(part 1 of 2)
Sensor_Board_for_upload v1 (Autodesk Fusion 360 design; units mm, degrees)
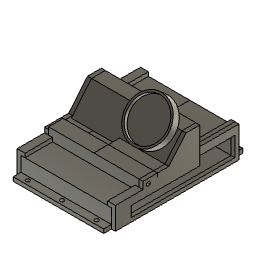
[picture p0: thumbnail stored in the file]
description: KiCad electronic assembly
part number: Sensor_Board 1
description: Part Number
part number: Sensor_Board 1.1.1
part number: Sensor_Board 1.1.2
part number: PinSocket-01x06_P2.54mm_Horizontal_SMD
part number: SoC_nRF_Sense
part number: Mic_nRF_Sense
part number: Antenna_nRF_Sense
part number: Board
part number: USB
part number: Contact
base_feature "Base Feature1"
base_feature "Base Feature1"
base_feature "Base Feature1"
base_feature "Base Feature1"
base_feature "Base Feature1"
base_feature "Base Feature1"
base_feature "Base Feature1"
place_component sketch "Sketch7"
base_feature "Base Feature1" sketch "Sketch7"
place_component sketch "Sketch7"
base_feature "Base Feature1" sketch "Sketch7"
base_feature "Base Feature1"
base_feature "Base Feature1"
base_feature "Base Feature1"
base_feature "Base Feature1"
base_feature "Base Feature1"
base_feature "Base Feature1"
base_feature "Base Feature1"
base_feature "Base Feature1"
base_feature "Base Feature1"
base_feature "Base Feature1"
place_component sketch "Sketch7"
base_feature "Base Feature1" sketch "Sketch7"
place_component sketch "Sketch7"
base_feature "Base Feature1" sketch "Sketch7"
place_component sketch "Sketch7"
base_feature "Base Feature1" sketch "Sketch7"
sketch "Sketch1" plane through (0, 0, 1.51) normal (0, 0, 1) x axis (-1, 0, 0)
  line L1 (-176.42, 128.48) -> (-136.51, 128.48)
  line L2 (-176.42, 91.11) -> (-176.42, 128.48)
  line L3 (-136.51, 91.11) -> (-176.42, 91.11)
  line L4 (-136.51, 128.48) -> (-136.51, 91.11)
  line L5 (-176.42, 91.11) -> (-136.51, 91.11)
  line L6 (-176.42, 128.48) -> (-176.42, 91.11)
  line L7 (-136.51, 128.48) -> (-176.42, 128.48)
  line L8 (-136.51, 91.11) -> (-136.51, 128.48)
  line L9 (-139, 115) -> (-157, 115)
  line L10 (-153, 101) -> (-143, 101)
  line L11 (-153, 92) -> (-153, 101)
  line L12 (-143, 92) -> (-153, 92)
  line L13 (-143, 101) -> (-143, 92)
  line L14 (-157.9717, 100.9445) -> (-136.51, 100.9445)
  line L15 (-157.9717, 115.3711) -> (-157.9717, 100.9445)
  line L16 (-136.51, 115.3711) -> (-157.9717, 115.3711)
  line L17 (-136.51, 100.9445) -> (-136.51, 115.3711)
  line L18 (-176.42, 92) -> (-162, 92)
  line L19 (-176.42, 127.4772) -> (-176.42, 92)
  line L20 (-162, 127.4772) -> (-176.42, 127.4772)
  line L21 (-162, 92) -> (-162, 127.4772)
  line L22 (-136.51, 107.3445) -> (-136.51, 100.9445)
  line L23 (-134, 107.4) -> (-134, 101)
  line L24 (-136.51, 112.3445) -> (-136.51, 107.3445)
  line L25 (-154.6841, 107.3445) -> (-136.51, 107.3445)
  line L26 (-154.6841, 112.46) -> (-154.6841, 107.3445)
  line L27 (-136.51, 112.46) -> (-154.6841, 112.46)
  line L28 (-136.51, 107.3445) -> (-136.51, 112.46)
  line L29 (-154.6841, 107.3445) -> (-136.51, 107.3445)
  line L30 (-154.6841, 112.46) -> (-154.6841, 107.3445)
  line L31 (-136.51, 112.46) -> (-154.6841, 112.46)
  line L32 (-136.51, 107.3445) -> (-136.51, 112.46)
  circle C1 centre (-140.465, 112.46) radius 0.4
  circle C2 centre (-140.465, 109.92) radius 0.4
  circle C3 centre (-140.465, 107.38) radius 0.4
  circle C4 centre (-155.7, 112.46) radius 0.4
  circle C5 centre (-155.7, 109.92) radius 0.4
  circle C6 centre (-155.7, 107.38) radius 0.4
  circle C7 centre (-140.465, 104.84) radius 0.4
  circle C8 centre (-140.465, 102.3) radius 0.4
  circle C9 centre (-140.465, 99.76) radius 0.4
  circle C10 centre (-140.465, 97.22) radius 0.4
  circle C11 centre (-155.7, 104.84) radius 0.4
  circle C12 centre (-155.7, 102.3) radius 0.4
  circle C13 centre (-155.7, 99.76) radius 0.4
  circle C14 centre (-155.7, 97.22) radius 0.4
  point P3 (-176.42, 128.48)
  point P22 (-176.42, 128.48)
  point P5 (-136.51, 91.11)
  point P20 (-136.51, 91.11)
  point P30 (-136.51, 100.9445)
  point P36 (-176.42, 127.4772)
  point P38 (-136.51, 107.3445)
  point P39 (-134, 101)
  point P40 (-134, 107.4)
  point P41 (-136.51, 112.3445)
  horizontal L5
  vertical L6
  horizontal L7
  vertical L8
  coincident P3 P22
  coincident P5 P20
  horizontal L9
  horizontal L10
  vertical L11
  horizontal L12
  vertical L13
  horizontal L14
  vertical L15
  horizontal L16
  vertical L17
  coincident L4 P30
  horizontal L18
  vertical L19
  horizontal L20
  vertical L21
  coincident L6 P36
  perpendicular L14 L22
  vertical L23
  parallel L4 L24
  horizontal L25
  vertical L26
  horizontal L27
  vertical L28
  horizontal L29
  vertical L30
  horizontal L31
  vertical L32
  dimension "d24" distance P30 P38 = 6.4
  dimension "d25" distance P39 P40 = 6.4
  dimension "d26" distance P38 P41 = 5
extrude "Extrude1" new body sketch "Sketch1" profile of L4 C1 C2 C3 C4 C5 C6 C7 C8 C11 C12 L8 L10 L11 L13 L14 L15 L16 L17 along normal blind 8.1
extrude "Extrude2" new body sketch "Sketch1" profile of L11 L12 L13 L14 along normal blind 4.7
extrude "Extrude3" new body sketch "Sketch1" profile of L2 L6 L18 L19 L20 L21 along normal blind 2.7
extrude "Extrude4" add of existing geometry to an object
extrude "Extrude5" add of existing geometry to an object
extrude "Extrude6" add of existing geometry to an object
extrude "Extrude7" add of existing geometry blind 1
extrude "Extrude8" add of existing geometry to an object
extrude "Extrude9" add of existing geometry blind 1.1
extrude "Extrude10" add sketch "Sketch1" profile of L1 L2 L3 L4 C1 C2 C3 C4 C5 C6 C7 C8 C9 C10 C11 C12 C13 C14 L5 L6 L7 L8 L10 L11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 against normal blind 1.3
shell "Shell1" outerThickness 2
delete_face "DeleteFace1"
extrude "Extrude11" cut of existing geometry blind -11
extrude "Extrude1" cut sketch "Sketch1" profile of L4 C1 C2 C3 L8 L17 L29 L30 L31 L32 along normal blind 10
extrude "Extrude2" cut sketch "Sketch1" profile of L4 C1 C2 C3 L8 L17 L29 L30 L31 L32 along normal blind 10
extrude "Extrude3" cut sketch "Sketch1" profile of L4 C1 C2 C3 L8 L17 L29 L30 L31 L32 along normal blind 12.5
extrude "Extrude13" add of existing geometry to an object
sketch "Sketch2" plane through (178.42, 0, 0) normal (1, 0, 0) x axis (0, 1, 0)
  line L1 (-89, 6.21) -> (-89, -1.79)
  line L2 (-130.5772, 6.21) -> (-89, 6.21)
  line L3 (-130.5772, -0.49) -> (-130.5772, 6.21)
  line L4 (-130.48, -0.49) -> (-130.5772, -0.49)
  line L5 (-130.48, -1.79) -> (-130.48, -0.49)
  line L6 (-89, -1.79) -> (-130.48, -1.79)
  line L7 (-129.7046, 5.3373) -> (-89.8727, 5.3373)
  line L8 (-129.7046, 0.3827) -> (-129.7046, 5.3373)
  line L9 (-129.6073, 0.3827) -> (-129.7046, 0.3827)
  line L10 (-129.6073, -0.9173) -> (-129.6073, 0.3827)
  line L11 (-89.8727, -0.9173) -> (-129.6073, -0.9173)
  line L12 (-89.8727, 5.3373) -> (-89.8727, -0.9173)
  dimension "d57" = -0.8727
extrude "Extrude14" cut sketch "Sketch2" profile of L7 L8 L10 L11 L12 L9 against normal blind 4
sketch "Sketch3" plane through (0, -89, 0) normal (0, 1, 0) x axis (-1, 0, 0)
  line L1 (-159.9717, 8.21) -> (-136.51, 8.21)
  line L2 (-159.9717, 6.21) -> (-159.9717, 8.21)
  line L3 (-178.42, 6.21) -> (-159.9717, 6.21)
  line L4 (-178.42, -1.79) -> (-178.42, 6.21)
  line L5 (-136.51, -1.79) -> (-178.42, -1.79)
  line L6 (-136.51, 8.21) -> (-136.51, -1.79)
  line L7 (-141.3021, 7) -> (-155, 7)
  line L8 (-141.3021, 2.7647) -> (-141.3021, 7)
  line L9 (-155, 2.7647) -> (-141.3021, 2.7647)
  line L10 (-155, 7) -> (-155, 2.7647)
  horizontal L7
  vertical L8
  horizontal L9
  vertical L10
extrude "Extrude15" cut sketch "Sketch3" profile of L7 L8 L9 L10 against normal blind 2
extrude "Extrude16" add of existing geometry blind 10
extrude "Extrude17" add of existing geometry to an object
extrude "Extrude18" add of existing geometry to an object
sketch "Sketch4" plane through (136.51, 0, 0) normal (-1, 0, 0) x axis (0, -1, 0)
  line L1 (112.46, 9.61) -> (112.46, 11.61)
  line L2 (115.3711, 9.61) -> (112.46, 9.61)
  line L3 (115.3711, 4.21) -> (115.3711, 9.61)
  line L4 (128.5772, 4.21) -> (115.3711, 4.21)
  line L5 (128.5772, 1.51) -> (128.5772, 4.21)
  line L6 (128.48, 1.51) -> (128.5772, 1.51)
  line L7 (128.48, 0.21) -> (128.48, 1.51)
  line L8 (91.11, 0.21) -> (128.48, 0.21)
  line L9 (91.11, 1.51) -> (91.11, 0.21)
  line L10 (91, 1.51) -> (91.11, 1.51)
  line L11 (91, 6.21) -> (91, 1.51)
  line L12 (100.9445, 6.21) -> (91, 6.21)
  line L13 (100.9445, 9.61) -> (100.9445, 6.21)
  line L14 (107.3445, 9.61) -> (100.9445, 9.61)
  line L15 (107.3445, 11.61) -> (107.3445, 9.61)
  line L16 (89, 11.61) -> (107.3445, 11.61)
  line L17 (89, -1.79) -> (89, 11.61)
  line L18 (130.48, -1.79) -> (89, -1.79)
  line L19 (130.48, -0.49) -> (130.48, -1.79)
  line L20 (130.5772, -0.49) -> (130.48, -0.49)
  line L21 (130.5772, 6.21) -> (130.5772, -0.49)
  line L22 (117.3711, 6.21) -> (130.5772, 6.21)
  line L23 (117.3711, 11.61) -> (117.3711, 6.21)
  line L24 (112.46, 11.61) -> (117.3711, 11.61)
  line L25 (97.0599, 23.8667) -> (107.3445, 11.61)
  line L26 (123.3445, 11.61) -> (107.3445, 11.61)
  line L27 (97.0599, 11.61) -> (97.0599, 23.8667)
  line L28 (96, 23.8667) -> (97.0599, 23.8667)
  line L29 (96, 11.61) -> (96, 23.8667)
  point P17 (107.3445, 11.61)
  point P26 (107.3445, 11.61)
  point P29 (97.0599, 11.61)
  point P31 (96, 11.61)
  point P27 (97.0599, 23.8667)
  horizontal L26
  coincident P17 P26
  coincident L16 P29
  perpendicular L16 L27
  perpendicular L27 L28
  coincident L16 P31
  perpendicular L16 L29
  dimension "d68" angle L25 L26 = 130
  dimension "d69" distance P26 P27 = 16
extrude "Extrude19" add sketch "Sketch4" profile of L16 L25 L27 L28 L29 to an object
extrude "Extrude20" add of existing geometry blind 2
extrude "Extrude21" add of existing geometry blind 5
sketch "Sketch5" plane through (0, 0, -0.49) normal (0, 0, 1) x axis (-1, 0, 0)
  line L1 (-136.51, 130.5772) -> (-178.42, 130.5772)
  line L2 (-136.51, 135.48) -> (-136.51, 130.5772)
  line L3 (-178.42, 135.48) -> (-136.51, 135.48)
  line L4 (-178.42, 130.5772) -> (-178.42, 135.48)
  circle C1 centre (-176.1314, 133.0286) radius 1
  circle C2 centre (-157.6314, 133.0286) radius 1
  circle C3 centre (-139.1314, 133.0286) radius 1
  dimension "d86" diameter C1 = 2
  dimension "d89" R-Pattern1-uDistance = 37
  dimension "d90" R-Pattern1-vDistance = 0
extrude "Extrude22" cut sketch "Sketch5" profile of C1 C2 C3 against normal blind 2
extrude "Extrude23" add of existing geometry blind 19
offset_faces "OffsetFaces1" distance -1
extrude "Extrude24" cut of existing geometry blind -0.5 taper 1 (= "deg")
sketch "Sketch6" plane through (0, -67.9431, 57.011) normal (0, -0.766, 0.6428) x axis (1, 0, 0)
  line L1 (136.51, -43.6488) -> (178.9717, -43.6488)
  line L2 (136.51, -59.742) -> (136.51, -43.6488)
  line L3 (154.6841, -59.742) -> (136.51, -59.742)
  line L4 (154.6841, -59.2668) -> (154.6841, -59.742)
  line L5 (178.9717, -59.2668) -> (154.6841, -59.2668)
  line L6 (178.9717, -43.6488) -> (178.9717, -59.2668)
  line L7 (155.6335, -43.6488) -> (141.6335, -43.6488)
  line L8 (155.6335, -57.6488) -> (155.6335, -43.6488)
  line L9 (141.6335, -57.6488) -> (155.6335, -57.6488)
  line L10 (141.6335, -43.6488) -> (141.6335, -57.6488)
  point P8 (141.6335, -43.6488)
  point P9 (155.6335, -43.6488)
  point P11 (141.6335, -57.6488)
  horizontal L7
  vertical L8
  horizontal L9
  vertical L10
  coincident L1 P8
  dimension "d100" distance P8 P9 = 14
  dimension "d101" distance P8 P11 = 14
extrude "Extrude25" new body sketch "Sketch6" profile of L1 L7 L8 L9 L10 along normal blind 4
extrude "Extrude26" add of existing geometry blind 3
extrude "Extrude27" add of existing geometry to an object
sketch "Sketch7" plane through (0, -89, 0) normal (0, 1, 0) x axis (-1, 0, 0)
  line L1 (-141.3021, 2.7647) -> (-141.3021, 7)
  line L2 (-155, 2.7647) -> (-141.3021, 2.7647)
  line L3 (-155, 7) -> (-155, 2.7647)
  line L4 (-141.3021, 7) -> (-155, 7)
  line L5 (-136.51, 11.61) -> (-136.51, -1.79)
  line L6 (-181.9717, 11.61) -> (-136.51, 11.61)
  line L7 (-181.9717, -1.79) -> (-181.9717, 11.61)
  line L8 (-136.51, -1.79) -> (-181.9717, -1.79)
  line L9 (-156.7, 1.0647) -> (-139.6021, 1.0647)
  line L10 (-156.7, 8.7) -> (-156.7, 1.0647)
  line L11 (-139.6021, 8.7) -> (-156.7, 8.7)
  line L12 (-139.6021, 1.0647) -> (-139.6021, 8.7)
  dimension "d108" = -1.7
extrude "Extrude4" cut sketch "Sketch7" profile of L1 L2 L3 L4 L11 L12 L10 L9 against normal blind 11
extrude "Extrude29" cut of existing geometry to an object
position "Position1"
extrude "Extrude30" add of existing geometry to an object
extrude "Extrude31" add of existing geometry blind 7
extrude "Extrude32" add blind 7
extrude "Extrude33" cut of existing geometry to an object
extrude "Extrude34" add of existing geometry to an object
sketch "Sketch8" plane through (0, -67.9431, 57.011) normal (0, -0.766, 0.6428) x axis (1, 0, 0)
  circle C1 centre (170, -46) radius 11.5
  circle C2 centre (170, -46) radius 10.25
  concentric C1 C2
  dimension "d135" diameter C1 = 23
  dimension "d136" diameter C2 = 20.5
extrude "Extrude35" add sketch "Sketch8" against normal blind 2
extrude "Extrude36" add sketch "Sketch8" along normal blind 2
sketch "Sketch9" plane through (0, 0, 0) normal (1, 0, 0) x axis (0, 1, 0)
  line L1 (-129.7046, 5.3373) -> (-129.7046, 0.3827)
  line L2 (-89.8727, 5.3373) -> (-129.7046, 5.3373)
  line L3 (-89.8727, -0.9173) -> (-89.8727, 5.3373)
  line L4 (-129.6073, -0.9173) -> (-89.8727, -0.9173)
  line L5 (-129.6073, 0.3827) -> (-129.6073, -0.9173)
  line L6 (-129.7046, 0.3827) -> (-129.6073, 0.3827)
  line L7 (-106.0391, 11.61) -> (-96, 23.5741)
  line L8 (-117.3711, 11.61) -> (-106.0391, 11.61)
  line L9 (-117.3711, 6.21) -> (-117.3711, 11.61)
  line L10 (-130.5772, 6.21) -> (-117.3711, 6.21)
  line L11 (-130.5772, -0.49) -> (-130.5772, 6.21)
  line L12 (-135.48, -0.49) -> (-130.5772, -0.49)
  line L13 (-135.48, -1.79) -> (-135.48, -0.49)
  line L14 (-89, -1.79) -> (-135.48, -1.79)
  line L15 (-89, 23.5741) -> (-89, -1.79)
  line L16 (-96, 23.5741) -> (-89, 23.5741)
  line L17 (-72, -1.79) -> (-89, -1.79)
  line L18 (-72, -0.79) -> (-72, -1.79)
  line L19 (-89, -0.79) -> (-72, -0.79)
  line L20 (-89, -1.79) -> (-89, -0.79)
  point P16 (-89, -1.79)
  point P18 (-89, -1.79)
  point P19 (-72, -1.79)
  point P21 (-89, -0.79)
  horizontal L17
  vertical L18
  horizontal L19
  vertical L20
  coincident P16 P18
  dimension "d141" distance P18 P19 = 17
  dimension "d142" distance P18 P21 = 1
sketch "Sketch1" plane through (-0.0036, 0, 0) normal (1, 0, 0) x axis (0, 1, 0)
  line L1 (-106.2762, 11.1776) -> (-106.2762, 10.0416)
  line L2 (-71.0417, 0.1416) -> (-91.0417, 0.1416)
  line L3 (-115.7809, 5.5) -> (-115.7809, 10)
  line L4 (-129.7809, 5.5) -> (-115.7809, 5.5)
  line L5 (-129.7809, 0.1416) -> (-129.7809, 5.5)
  line L6 (-110.3917, 8.5692) -> (-110.3917, 11.1776)
  line L7 (-106.2762, 8.5692) -> (-110.3917, 8.5692)
  line L8 (-106.2762, 11.1776) -> (-106.2762, 8.5692)
  line L9 (-88.9317, 10) -> (-88.9317, 23.5057)
  line L10 (-106.2762, 10.0416) -> (-106.2762, 11.1776)
  line L11 (-88.9317, 23.5057) -> (-88.9317, 10)
  line L12 (-71.0417, 0.1416) -> (-71.0417, 10)
  line L13 (-129.7809, 0.1416) -> (-91.0417, 0.1416)
  line L14 (-106.2762, 11.1776) -> (-95.9317, 23.5057)
  line L15 (-71.0417, 10) -> (-88.9317, 10.0211)
  line L16 (-95.9317, 23.5057) -> (-88.9317, 23.5057)
  line L17 (-135.7809, 0.1416) -> (-129.7809, 0.1416)
  line L18 (-100.5425, 11.1416) -> (-100.5425, 10.0348)
  line L19 (-106.2762, 11.1776) -> (-100.5425, 11.1416)
  line L20 (-110.3917, 11.1776) -> (-110.3917, 9.8734)
  line L21 (-116.3456, 11.1416) -> (-100.5425, 11.1416)
  line L22 (-115.7809, 11.1416) -> (-115.7809, 10)
  line L23 (-110.3917, 11.1776) -> (-115.7809, 11.1416)
  line L24 (-100.5425, 0.1416) -> (-100.5425, 11.1416)
  line L25 (-110.4051, 13.1776) -> (-117.7809, 13.1283)
  line L26 (-117.7809, 13.1283) -> (-117.7809, 10)
  line L27 (-117.7809, 7.5) -> (-117.7809, 10)
  line L28 (-131.7809, 7.5) -> (-117.7809, 7.5)
  line L29 (-131.7809, 0.1416) -> (-131.7809, 7.5)
  line L30 (-110.3917, 11.1776) -> (-110.4051, 13.1776)
  line L31 (-135.7809, 0.1416) -> (-131.7809, 0.1416)
  line L32 (-131.7809, -4.6856) -> (-131.7809, 1.0452)
  line L33 (-128, -1.8584) -> (-131.727, -1.8584)
  line L34 (-131.7809, -1.8584) -> (-71.0417, -1.8584)
  line L35 (-131.7809, 0.1416) -> (-131.7809, -1.8584)
  line L36 (-135.78, -1.8416) -> (-131.7809, -1.8584)
  line L37 (-135.7809, 0.1416) -> (-135.78, -1.8416)
  line L38 (-71.0417, -1.8584) -> (-71.0417, 0.5196)
  line L39 (-69.0417, 11.9976) -> (-88.9293, 12.0211)
  line L40 (-69.0417, -1.8584) -> (-69.0417, 11.9976)
  line L41 (-69.0417, -1.8584) -> (-91.0417, -1.8584)
  line L42 (-129.7809, -1.8584) -> (-91.0417, -1.8584)
  line L43 (-88.9317, 10) -> (-88.9293, 12.0211)
  line L44 (-65.0417, -1.8584) -> (-69.0417, -1.8584)
  line L45 (-65.0417, 0.319) -> (-65.0417, -1.8584)
  line L46 (-69.0417, 0.319) -> (-65.0417, 0.319)
  line L47 (-69.0417, -1.8584) -> (-69.0417, 0.319)
  line L48 (-100.5425, 10.0348) -> (-88.9317, 10)
  line L49 (-71.0417, 0.319) -> (-69.0417, 0.319)
  point P3 (-106.2762, 11.1776)
  point P11 (-106.2762, 11.1776)
  point P2 (-106.2762, 10.0416)
  point P18 (-106.2762, 10.0416)
  point P21 (-106.2762, 11.1776)
  point P23 (-110.3917, 9.8734)
  point P25 (-115.7809, 11.1416)
  point P26 (-100.5425, 0.1416)
  point P33 (-88.9317, 10.0211)
  point P35 (-131.7809, 1.0452)
  point P38 (-131.7809, -1.8584)
  point P40 (-71.0417, 0.5196)
  point P4 (-91.0417, 0.1416)
  point P5 (-71.0417, 0.1416)
  point P7 (-115.7809, 10)
  point P8 (-115.7809, 5.5)
  point P9 (-129.7809, 5.5)
  point P10 (-129.7809, 0.1416)
  point P19 (-135.7809, 0.1416)
  point P44 (-69.0417, -1.8584)
  point P47 (-65.0417, -1.8584)
  vertical L6
  horizontal L7
  vertical L8
  coincident P3 P11
  coincident P2 P18
  perpendicular L5 L13
  horizontal L16
  perpendicular L5 L17
  vertical L18
  coincident P3 P21
  midpoint L6 P23
  perpendicular L18 L21
  coincident L21 P25
  perpendicular L21 L22
  coincident L13 P26
  perpendicular L13 L24
  perpendicular L23 L30
  coincident L9 P33
  parallel L17 L31
  coincident L29 P35
  perpendicular L31 L32
  perpendicular L32 L33
  coincident L32 P38
  perpendicular L32 L34
  perpendicular L17 L35
  coincident L12 P40
  perpendicular L34 L38
  horizontal L44
  vertical L45
  horizontal L46
  vertical L47
  horizontal L49
  perpendicular L38 L49
  dimension "d143" distance P4 P5 = 20
  dimension "d145" distance P7 P8 = 4.5
  dimension "d146" distance P8 P9 = 14
  dimension "d147" distance P10 P19 = 6
  dimension "d150" = -2
  dimension "d154" = 2
  dimension "d155" distance P44 P47 = 4
extrude "Extrude1" new body sketch "Sketch1" profile of L2 L3 L4 L5 L9 L11 L12 L13 L14 L15 L16 L17 L18 L19 L22 L23 L24 L26 L28 L27 L29 L25 L30 L31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 along normal blind 23
sketch "Sketch2" plane through (22.9964, 0, 0) normal (1, 0, 0) x axis (0, 1, 0)
  line L1 (-95.9317, 23.5057) -> (-88.9317, 23.5057)
  line L2 (-106.2762, 11.1776) -> (-95.9317, 23.5057)
  line L3 (-100.5425, 11.1416) -> (-106.2762, 11.1776)
  line L4 (-100.5425, 10.0348) -> (-100.5425, 11.1416)
  line L5 (-88.9317, 10) -> (-100.5425, 10.0348)
  line L6 (-88.9317, 23.5057) -> (-88.9317, 10)
  line L7 (-65.0417, -1.8584) -> (-131.7809, -1.8584)
  line L8 (-65.0417, 0.319) -> (-65.0417, -1.8584)
  line L9 (-69.0417, 0.319) -> (-65.0417, 0.319)
  line L10 (-69.0417, 11.9976) -> (-69.0417, 0.319)
  line L11 (-88.9293, 12.0211) -> (-69.0417, 11.9976)
  line L12 (-88.9317, 10.0211) -> (-88.9293, 12.0211)
  line L13 (-71.0417, 10) -> (-88.9317, 10.0211)
  line L14 (-71.0417, 0.1416) -> (-71.0417, 10)
  line L15 (-129.7809, 0.1416) -> (-71.0417, 0.1416)
  line L16 (-129.7809, 5.5) -> (-129.7809, 0.1416)
  line L17 (-115.7809, 5.5) -> (-129.7809, 5.5)
  line L18 (-115.7809, 11.1416) -> (-115.7809, 5.5)
  line L19 (-110.3917, 11.1776) -> (-115.7809, 11.1416)
  line L20 (-110.4051, 13.1776) -> (-110.3917, 11.1776)
  line L21 (-117.7809, 13.1283) -> (-110.4051, 13.1776)
  line L22 (-117.7809, 7.5) -> (-117.7809, 13.1283)
  line L23 (-131.7809, 7.5) -> (-117.7809, 7.5)
  line L24 (-131.7809, 0.1416) -> (-131.7809, 7.5)
  line L25 (-135.7809, 0.1416) -> (-131.7809, 0.1416)
  line L26 (-135.78, -1.8416) -> (-135.7809, 0.1416)
  line L27 (-131.7809, -1.8584) -> (-135.78, -1.8416)
  line L28 (-117.7224, 5.5) -> (-117.7224, 11.9976)
  line L29 (-69.0417, 5.5) -> (-117.7224, 5.5)
  line L30 (-69.0417, 11.9976) -> (-69.0417, 5.5)
  line L31 (-110.3917, 13.1776) -> (-110.4051, 13.1776)
  line L32 (-110.3917, 11.1776) -> (-110.3917, 13.1776)
  line L33 (-110.4051, 11.1776) -> (-110.3917, 11.1776)
  line L34 (-110.4051, 13.1776) -> (-110.4051, 11.1776)
  line L35 (-110.3917, 13.1776) -> (-110.4051, 13.1776)
  line L36 (-110.3917, 11.1776) -> (-110.3917, 13.1776)
  line L37 (-110.4051, 11.1776) -> (-110.3917, 11.1776)
  line L38 (-110.4051, 13.1776) -> (-110.4051, 11.1776)
  line L39 (-88.9374, 11.9976) -> (-88.9374, 13.1283)
  line L40 (-117.7809, 8.2745) -> (-90.4296, 8.2745)
  line L41 (-117.7809, 13.1283) -> (-117.7809, 8.2745)
  line L42 (-95.9317, 23.5057) -> (-106.2762, 11.1776)
  line L43 (-88.9293, 12.0211) -> (-88.9317, 23.5057)
  line L44 (-88.9317, 23.5057) -> (-95.9317, 23.5057)
  line L45 (-88.9317, 23.5057) -> (-95.9317, 23.5057)
  line L46 (-97.5297, 10.0174) -> (-90.998, 10.0174)
  line L47 (-95.2322, 22.0057) -> (-102.3675, 13.5022)
  line L48 (-90.4314, 22.0057) -> (-95.2322, 22.0057)
  line L49 (-90.4296, 13.519) -> (-90.4314, 22.0057)
  line L50 (-102.3675, 13.5022) -> (-99.0604, 13.5068)
  line L51 (-90.998, 11.9976) -> (-90.998, 12.0182)
  line L52 (-99.0604, 10.0174) -> (-90.998, 10.0174)
  line L53 (-99.0604, 13.5068) -> (-99.0604, 10.0174)
  line L54 (-99.0604, 8.2745) -> (-99.0604, 10.0174)
  line L55 (-102.3675, 13.5022) -> (-99.0604, 13.5068)
  line L56 (-88.9374, 12.0211) -> (-88.9293, 12.0211)
  line L57 (-105.5881, 11.9976) -> (-99.0604, 12.0068)
  line L58 (-88.9374, 11.9976) -> (-69.0417, 11.9976)
  line L59 (-117.7224, 11.9976) -> (-99.0604, 11.9976)
  line L60 (-99.0604, 13.1283) -> (-117.7809, 13.1283)
  line L61 (-88.9374, 12.0211) -> (-88.9293, 12.0211)
  line L62 (-105.5881, 11.9976) -> (-99.0604, 12.0068)
  line L63 (-90.4296, 8.2745) -> (-90.4296, 13.519)
  point P31 (-117.7224, 5.5)
  point P12 (-69.0417, 11.9976)
  point P29 (-69.0417, 11.9976)
  point P21 (-110.3917, 11.1776)
  point P35 (-110.3917, 11.1776)
  point P22 (-110.4051, 13.1776)
  point P33 (-110.4051, 13.1776)
  point P23 (-117.7809, 13.1283)
  point P39 (-117.7809, 13.1283)
  point P4 (-106.2762, 11.1776)
  point P42 (-106.2762, 11.1776)
  point P3 (-95.9317, 23.5057)
  point P43 (-95.9317, 23.5057)
  point P2 (-88.9317, 23.5057)
  point P44 (-88.9317, 23.5057)
  point P13 (-88.9293, 12.0211)
  point P45 (-88.9293, 12.0211)
  point P46 (-95.9317, 23.5057)
  point P47 (-88.9317, 23.5057)
  point P48 (-88.9293, 12.0211)
  point P49 (-105.5881, 11.9976)
  point P58 (-99.0604, 8.2745)
  point P60 (-99.0604, 12.0068)
  point P62 (-99.0604, 11.9976)
  point P63 (-99.0604, 13.1283)
  point P64 (-88.9374, 12.0211)
  horizontal L58
  vertical L28
  horizontal L29
  vertical L30
  coincident L17 P31
  coincident P12 P29
  horizontal L31
  vertical L32
  horizontal L33
  vertical L34
  coincident P21 P35
  coincident P22 P33
  horizontal L35
  vertical L36
  horizontal L37
  vertical L38
  horizontal L60
  vertical L39
  horizontal L40
  vertical L41
  coincident P23 P39
  coincident P4 P42
  coincident P3 P43
  coincident P2 P44
  coincident P13 P45
  coincident P3 P46
  coincident P2 P47
  coincident P13 P48
  coincident P49 L58
  coincident L42 P49
  horizontal L46
  vertical L51
  horizontal L52
  vertical L53
  coincident L40 P58
  perpendicular L40 L54
  parallel L50 L55
  coincident L53 P60
  collinear L56 L57
  coincident L53 P62
  collinear L58 L59
  coincident L53 P63
  collinear L61 L62
  coincident L39 P64
  perpendicular L40 L63
sketch "Sketch3" plane through (40.9964, 0, 0) normal (1, 0, 0) x axis (0, 1, 0)
  line L1 (-95.2322, 22.0057) -> (-102.3675, 13.5022)
  line L2 (-90.4314, 22.0057) -> (-95.2322, 22.0057)
  line L3 (-90.4296, 13.519) -> (-90.4314, 22.0057)
  line L4 (-102.3675, 13.5022) -> (-99.0604, 13.5068)
  line L5 (-88.9317, 12.0211) -> (-88.9374, 12.0211)
  line L6 (-88.9317, 11.9976) -> (-88.9317, 10)
  line L7 (-95.9317, 23.5057) -> (-88.9317, 23.5057)
  line L8 (-104.6394, 13.1283) -> (-95.9317, 23.5057)
  line L9 (-110.3917, 13.1283) -> (-104.6394, 13.1283)
  line L10 (-110.3917, 11.1776) -> (-110.3917, 13.1283)
  line L11 (-110.4051, 11.1776) -> (-110.3917, 11.1776)
  line L12 (-110.4051, 13.1283) -> (-110.4051, 11.1776)
  line L13 (-117.7809, 13.1283) -> (-110.4051, 13.1283)
  line L14 (-117.7809, 7.5) -> (-117.7809, 13.1283)
  line L15 (-131.7809, 7.5) -> (-117.7809, 7.5)
  line L16 (-131.7809, 0.1416) -> (-131.7809, 7.5)
  line L17 (-135.7809, 0.1416) -> (-131.7809, 0.1416)
  line L18 (-135.78, -1.8416) -> (-135.7809, 0.1416)
  line L19 (-131.7809, -1.8584) -> (-135.78, -1.8416)
  line L20 (-65.0417, -1.8584) -> (-131.7809, -1.8584)
  line L21 (-65.0417, 0.319) -> (-65.0417, -1.8584)
  line L22 (-69.0417, 0.319) -> (-65.0417, 0.319)
  line L23 (-69.0417, 11.9976) -> (-69.0417, 0.319)
  line L24 (-88.9293, 11.9976) -> (-69.0417, 11.9976)
  line L25 (-88.9317, 10.0211) -> (-88.9293, 11.9976)
  line L26 (-71.0417, 10) -> (-88.9317, 10.0211)
  line L27 (-71.0417, 0.1416) -> (-71.0417, 10)
  line L28 (-129.7809, 0.1416) -> (-71.0417, 0.1416)
  line L29 (-129.7809, 5.5) -> (-129.7809, 0.1416)
  line L30 (-115.7809, 5.5) -> (-129.7809, 5.5)
  line L31 (-115.7809, 8.2745) -> (-115.7809, 5.5)
  line L32 (-99.0604, 8.2745) -> (-115.7809, 8.2745)
  line L33 (-99.0604, 11.9976) -> (-99.0604, 8.2745)
  line L34 (-105.5881, 11.9976) -> (-99.0604, 11.9976)
  line L35 (-99.0604, 12.0068) -> (-105.5881, 11.9976)
  line L36 (-99.0604, 13.5068) -> (-99.0604, 12.0068)
  line L37 (-90.4296, 10.0045) -> (-90.4296, 13.519)
  line L38 (-88.9317, 10) -> (-90.4296, 10.0045)
  line L39 (-88.9374, 11.9976) -> (-88.9317, 11.9976)
  line L40 (-88.9374, 12.0211) -> (-88.9374, 11.9976)
  line L41 (-88.9317, 23.5057) -> (-88.9317, 12.0211)
extrude "Extrude3" add sketch "Sketch2" profile of L1 L2 L3 L4 L5 L6 L7 L8 L9 L10 L12 L13 L14 L15 L16 L17 L18 L19 L22 L23 L24 L25 L26 L27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 along normal blind 23
sketch "Sketch4" plane through (0, -67.8693, 56.9491) normal (0, -0.766, 0.6428) x axis (1, 0, 0)
  line L1 (-0.0036, -59.7504) -> (-0.0036, -43.6573)
  line L2 (22.9964, -59.7504) -> (-0.0036, -59.7504)
  line L3 (22.9964, -58.68) -> (22.9964, -59.7504)
  line L4 (22.9964, -57.2041) -> (22.9964, -58.68)
  line L5 (45.9964, -57.2041) -> (22.9964, -57.2041)
  line L6 (45.9964, -43.6573) -> (45.9964, -57.2041)
  line L7 (-0.0036, -43.6573) -> (45.9964, -43.6573)
  line L8 (32, -46) -> (23, -46)
  line L9 (33, -46) -> (23, -46)
  circle C1 centre (33, -46) radius 11
  circle C2 centre (33, -46) radius 10
  point P11 (33, -46)
  point P12 (33, -46)
  point P9 (23, -46)
  horizontal L8
  parallel L8 L9
  coincident P11 P12
  concentric C1 C2
  dimension "d166" distance P9 P11 = 10
  dimension "d168" diameter C1 = 22
  dimension "d169" diameter C2 = 20
extrude "Extrude5" add sketch "Sketch4" profile of L7 C1 C2 along normal blind 2
extrude "Extrude6" add sketch "Sketch4" profile of L7 C1 C2 along normal blind 4
sketch "Sketch5" plane through (0, 0, 0.319) normal (0, 0, 1) x axis (-1, 0, 0)
  line L1 (0.0036, 69.0417) -> (0.0036, 65.0417)
  line L2 (-45.9964, 69.0417) -> (0.0036, 69.0417)
  line L3 (-45.9964, 65.0417) -> (-45.9964, 69.0417)
  line L4 (0.0036, 65.0417) -> (-45.9964, 65.0417)
  line L5 (-40.5523, 66.9475) -> (-40.3442, 133.6687)
  circle C1 centre (-40.3442, 133.6687) radius 1
  circle C2 centre (-22.8442, 133.6687) radius 1
  circle C3 centre (-5.3442, 133.6687) radius 1
  circle C4 centre (-40.5523, 66.9475) radius 1
  circle C5 centre (-23.5523, 66.9475) radius 1
  circle C6 centre (-6.5523, 66.9475) radius 1
  point P6 (-40.3442, 133.6687)
  point P9 (-40.3442, 133.6687)
  point P10 (-40.5523, 66.9475)
  point P11 (-40.5523, 66.9475)
  coincident P6 P9
  coincident P10 P11
  dimension "d174" diameter C1 = 2
  dimension "d179" diameter C4 = 2
  dimension "d177" R-Pattern1-uDistance = 35
  dimension "d178" R-Pattern1-vDistance = 0
  dimension "d182" R-Pattern2-uDistance = 34
  dimension "d183" R-Pattern2-vDistance = 0
extrude "Extrude4" cut sketch "Sketch5" profile of C1 C2 C3 C4 C5 C6 against normal blind 3
sketch "Sketch6" plane through (45.9964, 0, 0) normal (1, 0, 0) x axis (0, 1, 0)
  line L1 (-99.0604, 13.5068) -> (-99.0604, 12.0068)
  line L2 (-102.3675, 13.5022) -> (-99.0604, 13.5068)
  line L3 (-95.2322, 22.0057) -> (-102.3675, 13.5022)
  line L4 (-90.4314, 22.0057) -> (-95.2322, 22.0057)
  line L5 (-90.4296, 13.519) -> (-90.4314, 22.0057)
  line L6 (-90.4296, 10.0045) -> (-90.4296, 13.519)
  line L7 (-88.9317, 10) -> (-90.4296, 10.0045)
  line L8 (-88.9317, 11.9976) -> (-88.9317, 10)
  line L9 (-88.9374, 11.9976) -> (-88.9317, 11.9976)
  line L10 (-88.9374, 12.0211) -> (-88.9374, 11.9976)
  line L11 (-88.9317, 12.0211) -> (-88.9374, 12.0211)
  line L12 (-88.9317, 23.5057) -> (-88.9317, 12.0211)
  line L13 (-95.9317, 23.5057) -> (-88.9317, 23.5057)
  line L14 (-104.6394, 13.1283) -> (-95.9317, 23.5057)
  line L15 (-110.3917, 13.1283) -> (-104.6394, 13.1283)
  line L16 (-110.3917, 11.1776) -> (-110.3917, 13.1283)
  line L17 (-110.4051, 11.1776) -> (-110.3917, 11.1776)
  line L18 (-110.4051, 13.1283) -> (-110.4051, 11.1776)
  line L19 (-117.7809, 13.1283) -> (-110.4051, 13.1283)
  line L20 (-117.7809, 7.5) -> (-117.7809, 13.1283)
  line L21 (-131.7809, 7.5) -> (-117.7809, 7.5)
  line L22 (-131.7809, 0.1416) -> (-131.7809, 7.5)
  line L23 (-135.7809, 0.1416) -> (-131.7809, 0.1416)
  line L24 (-135.78, -1.8416) -> (-135.7809, 0.1416)
  line L25 (-131.7809, -1.8584) -> (-135.78, -1.8416)
  line L26 (-65.0417, -1.8584) -> (-131.7809, -1.8584)
  line L27 (-65.0417, 0.319) -> (-65.0417, -1.8584)
  line L28 (-69.0417, 0.319) -> (-65.0417, 0.319)
  line L29 (-69.0417, 11.9976) -> (-69.0417, 0.319)
  line L30 (-88.9293, 11.9976) -> (-69.0417, 11.9976)
  line L31 (-88.9317, 10.0211) -> (-88.9293, 11.9976)
  line L32 (-71.0417, 10) -> (-88.9317, 10.0211)
  line L33 (-71.0417, 0.1416) -> (-71.0417, 10)
  line L34 (-129.7809, 0.1416) -> (-71.0417, 0.1416)
  line L35 (-129.7809, 5.5) -> (-129.7809, 0.1416)
  line L36 (-115.7809, 5.5) -> (-129.7809, 5.5)
  line L37 (-115.7809, 8.2745) -> (-115.7809, 5.5)
  line L38 (-99.0604, 8.2745) -> (-115.7809, 8.2745)
  line L39 (-99.0604, 11.9976) -> (-99.0604, 8.2745)
  line L40 (-105.5881, 11.9976) -> (-99.0604, 11.9976)
  line L41 (-99.0604, 12.0068) -> (-105.5881, 11.9976)
  circle C1 centre (-114.9874, 10.6426) radius 1
  dimension "d186" diameter C1 = 2
extrude "Extrude5" cut sketch "Sketch6" profile of C1 against normal blind 3
sketch "Sketch7" plane through (-0.0036, 0, 0) normal (-1, 0, 0) x axis (0, -1, 0)
  line L1 (88.9317, 23.5057) -> (95.9317, 23.5057)
  line L2 (88.9317, 10) -> (88.9317, 23.5057)
  line L3 (100.5425, 10.0348) -> (88.9317, 10)
  line L4 (100.5425, 11.1416) -> (100.5425, 10.0348)
  line L5 (106.2762, 11.1776) -> (100.5425, 11.1416)
  line L6 (95.9317, 23.5057) -> (106.2762, 11.1776)
  circle C1 centre (94.4863, 14.2587) radius 1
  dimension "d189" diameter C1 = 2
extrude "Extrude6" cut sketch "Sketch7" profile of C1 against normal blind 3
combine "Combine1"
sketch "Sketch8" plane through (0, 0, 0) normal (1, 0, 0) x axis (0, 1, 0)
  circle C1 centre (-40, 30) radius 11.15
  circle C2 centre (-40, 30) radius 11.65
  concentric C1 C2
  dimension "d192" diameter C1 = 22.3
  dimension "d193" diameter C2 = 23.3
extrude "Extrude3" add sketch "Sketch8" along normal blind 2
extrude "Extrude4" add sketch "Sketch8" profile of C1 along normal blind 0.5
combine "Combine1" bodies "Case"
sketch "Sketch9" plane through (45.9964, 0, 0) normal (1, 0, 0) x axis (0, 1, 0)
  line L1 (-99.0604, 13.5068) -> (-99.0604, 12.0068)
  line L2 (-102.3675, 13.5022) -> (-99.0604, 13.5068)
  line L3 (-95.2322, 22.0057) -> (-102.3675, 13.5022)
  line L4 (-90.4314, 22.0057) -> (-95.2322, 22.0057)
  line L5 (-90.4296, 13.519) -> (-90.4314, 22.0057)
  line L6 (-90.4296, 10.0045) -> (-90.4296, 13.519)
  line L7 (-88.9317, 10) -> (-90.4296, 10.0045)
  line L8 (-88.9317, 11.9976) -> (-88.9317, 10)
  line L9 (-88.9374, 11.9976) -> (-88.9317, 11.9976)
  line L10 (-88.9374, 12.0211) -> (-88.9374, 11.9976)
  line L11 (-88.9317, 12.0211) -> (-88.9374, 12.0211)
  line L12 (-88.9317, 23.5057) -> (-88.9317, 12.0211)
  line L13 (-95.9317, 23.5057) -> (-88.9317, 23.5057)
  line L14 (-104.6394, 13.1283) -> (-95.9317, 23.5057)
  line L15 (-110.3917, 13.1283) -> (-104.6394, 13.1283)
  line L16 (-110.3917, 11.1776) -> (-110.3917, 13.1283)
  line L17 (-110.4051, 11.1776) -> (-110.3917, 11.1776)
  line L18 (-110.4051, 13.1283) -> (-110.4051, 11.1776)
  line L19 (-117.7809, 13.1283) -> (-110.4051, 13.1283)
  line L20 (-117.7809, 7.5) -> (-117.7809, 13.1283)
  line L21 (-131.7809, 7.5) -> (-117.7809, 7.5)
  line L22 (-131.7809, 0.1416) -> (-131.7809, 7.5)
  line L23 (-135.7809, 0.1416) -> (-131.7809, 0.1416)
  line L24 (-135.78, -1.8416) -> (-135.7809, 0.1416)
  line L25 (-131.7809, -1.8584) -> (-135.78, -1.8416)
  line L26 (-65.0417, -1.8584) -> (-131.7809, -1.8584)
  line L27 (-65.0417, 0.319) -> (-65.0417, -1.8584)
  line L28 (-69.0417, 0.319) -> (-65.0417, 0.319)
  line L29 (-69.0417, 11.9976) -> (-69.0417, 0.319)
  line L30 (-88.9293, 11.9976) -> (-69.0417, 11.9976)
  line L31 (-88.9317, 10.0211) -> (-88.9293, 11.9976)
  line L32 (-71.0417, 10) -> (-88.9317, 10.0211)
  line L33 (-71.0417, 0.1416) -> (-71.0417, 10)
  line L34 (-129.7809, 0.1416) -> (-71.0417, 0.1416)
  line L35 (-129.7809, 5.5) -> (-129.7809, 0.1416)
  line L36 (-115.7809, 5.5) -> (-129.7809, 5.5)
  line L37 (-115.7809, 8.2745) -> (-115.7809, 5.5)
  line L38 (-99.0604, 8.2745) -> (-115.7809, 8.2745)
  line L39 (-99.0604, 11.9976) -> (-99.0604, 8.2745)
  line L40 (-105.5881, 11.9976) -> (-99.0604, 11.9976)
  line L41 (-135.7809, 0.1416) -> (-135.78, -1.8416)
  line L42 (-131.7809, 7.5) -> (-131.7809, 0.1416)
  line L43 (-117.7809, 13.1283) -> (-117.7809, 7.5)
  line L44 (-95.9317, 23.5057) -> (-104.6394, 13.1283)
  line L45 (-88.9317, 11.9976) -> (-88.9317, 23.5057)
  line L46 (-69.0417, 0.319) -> (-69.0417, 11.9976)
  line L47 (-65.0417, -1.8584) -> (-65.0417, 0.319)
  line L48 (-117.7809, 7.5) -> (-131.7809, 7.5)
  circle C1 centre (-114.9874, 10.6426) radius 1
  point P27 (-135.78, -1.8416)
  point P44 (-135.78, -1.8416)
  point P26 (-135.7809, 0.1416)
  point P45 (-135.7809, 0.1416)
  point P25 (-131.7809, 0.1416)
  point P46 (-131.7809, 0.1416)
  point P24 (-131.7809, 7.5)
  point P47 (-131.7809, 7.5)
  point P23 (-117.7809, 7.5)
  point P48 (-117.7809, 7.5)
  point P22 (-117.7809, 13.1283)
  point P49 (-117.7809, 13.1283)
  point P17 (-104.6394, 13.1283)
  point P50 (-104.6394, 13.1283)
  point P16 (-95.9317, 23.5057)
  point P51 (-95.9317, 23.5057)
  point P15 (-88.9317, 23.5057)
  point P52 (-88.9317, 23.5057)
  point P11 (-88.9317, 11.9976)
  point P53 (-88.9317, 11.9976)
  point P32 (-69.0417, 11.9976)
  point P54 (-69.0417, 11.9976)
  point P31 (-69.0417, 0.319)
  point P55 (-69.0417, 0.319)
  point P30 (-65.0417, 0.319)
  point P56 (-65.0417, 0.319)
  point P29 (-65.0417, -1.8584)
  point P57 (-65.0417, -1.8584)
  coincident P27 P44
  coincident P26 P45
  coincident P25 P46
  coincident P24 P47
  coincident P23 P48
  coincident P22 P49
  coincident P17 P50
  coincident P16 P51
  coincident P15 P52
  coincident P11 P53
  coincident P32 P54
  coincident P31 P55
  coincident P30 P56
  coincident P29 P57
sketch "Sketch10" plane through (0, 0, 0) normal (1, 0, 0) x axis (0, 1, 0)
  line L1 (-95.9317, 23.5057) -> (-90.3669, 30.1376)
  line L2 (-107.5724, 15.8558) -> (-100.5017, 24.2822)
  line L3 (-100.5017, 24.2822) -> (-93.4311, 32.7087)
  line L4 (-104.6394, 13.1283) -> (-104.5082, 13.2846)
  line L5 (-99.0604, 8.2745) -> (-99.0604, 10.0304)
  line L6 (-115.7809, 8.2745) -> (-99.0604, 8.2745)
  line L7 (-110.3917, 11.1776) -> (-110.3917, 13.1283)
  line L8 (-104.6394, 13.1283) -> (-110.3917, 13.1283)
  line L9 (-88.9317, 23.5057) -> (-88.9317, 10)
  line L10 (-99.0604, 10.0304) -> (-88.9317, 10)
  line L11 (-95.9317, 23.5057) -> (-88.9317, 23.5057)
  line L12 (-135.78, -1.8416) -> (-131.7809, -1.8584)
  line L13 (-135.7809, 0.1416) -> (-135.78, -1.8416)
  line L14 (-135.7809, 0.1416) -> (-131.7809, 0.1416)
  line L15 (-131.7809, 0.1416) -> (-131.7809, 7.5)
  line L16 (-131.7809, 7.5) -> (-117.7809, 7.5)
  line L17 (-117.7809, 7.5) -> (-117.7809, 13.1283)
  line L18 (-110.4051, 13.1776) -> (-117.7809, 13.1283)
  line L19 (-110.3917, 11.1776) -> (-110.4051, 13.1776)
  line L20 (-115.7809, 5.5) -> (-115.7809, 8.2745)
  line L21 (-129.7809, 5.5) -> (-115.7809, 5.5)
  line L22 (-129.7809, 0.1416) -> (-129.7809, 5.5)
  line L23 (-129.7809, 0.1416) -> (-71.0417, 0.1416)
  line L24 (-71.0417, 0.1416) -> (-71.0417, 10)
  line L25 (-71.0417, 10) -> (-88.9317, 10.0211)
  line L26 (-88.9317, 10.0211) -> (-88.9293, 12.0211)
  line L27 (-69.0417, 11.9976) -> (-88.9293, 12.0211)
  line L28 (-69.0417, 0.319) -> (-69.0417, 11.9976)
  line L29 (-69.0417, 0.319) -> (-65.0417, 0.319)
  line L30 (-65.0417, 0.319) -> (-65.0417, -1.8584)
  line L31 (-131.7809, -1.8584) -> (-65.0417, -1.8584)
  line L32 (-93.4311, 32.7087) -> (-90.3669, 30.1376)
  line L33 (-107.5724, 15.8558) -> (-104.5082, 13.2846)
  line L34 (-65.0417, -1.8584) -> (-135.78, -1.8416)
  line L35 (-135.7809, 0.1416) -> (-135.78, -1.8416)
  point P17 (-135.78, -1.8416)
  point P35 (-135.78, -1.8416)
  point P34 (-65.0417, -1.8584)
  point P36 (-65.0417, -1.8584)
  point P18 (-135.7809, 0.1416)
  point P37 (-135.7809, 0.1416)
  coincident P17 P35
  coincident P34 P36
  coincident P18 P37
sketch "Sketch1" plane through (0, 0, 0) normal (1, 0, 0) x axis (0, 1, 0)
  line L1 (-136, -2) -> (-65, -2)
  line L2 (-136, 0) -> (-136, -2)
  line L3 (-132, 0) -> (-136, 0)
  line L4 (-131.7809, -1.8584) -> (-65.0417, -1.8584)
  line L5 (-135.78, -1.8416) -> (-131.7809, -1.8584)
  line L6 (-135.7809, 0.1416) -> (-135.78, -1.8416)
  line L7 (-131.7809, 0.1416) -> (-135.7809, 0.1416)
  line L8 (-131.7809, 7.5) -> (-131.7809, 0.1416)
  line L9 (-117.7809, 7.5) -> (-131.7809, 7.5)
  line L10 (-117.7809, 13.1283) -> (-117.7809, 7.5)
  line L11 (-110.4051, 13.1776) -> (-117.7809, 13.1283)
  line L12 (-110.3917, 11.1776) -> (-110.4051, 13.1776)
  line L13 (-115.7809, 11.1416) -> (-110.3917, 11.1776)
  line L14 (-115.7809, 5.5) -> (-115.7809, 11.1416)
  line L15 (-129.7809, 5.5) -> (-115.7809, 5.5)
  line L16 (-129.7809, 0.1416) -> (-129.7809, 5.5)
  line L17 (-71.0417, 0.1416) -> (-129.7809, 0.1416)
  line L18 (-71.0417, 10) -> (-71.0417, 0.1416)
  line L19 (-88.9317, 10.0211) -> (-71.0417, 10)
  line L20 (-88.9293, 12.0211) -> (-88.9317, 10.0211)
  line L21 (-69.0417, 11.9976) -> (-88.9293, 12.0211)
  line L22 (-69.0417, 0.319) -> (-69.0417, 11.9976)
  line L23 (-65.0417, 0.319) -> (-69.0417, 0.319)
  line L24 (-65.0417, -1.8584) -> (-65.0417, 0.319)
  line L25 (-88.9317, 23.5057) -> (-95.9317, 23.5057)
  line L26 (-88.9317, 10) -> (-88.9317, 23.5057)
  line L27 (-100.5425, 10.0348) -> (-88.9317, 10)
  line L28 (-100.5425, 11.1416) -> (-100.5425, 10.0348)
  line L29 (-106.2762, 11.1776) -> (-100.5425, 11.1416)
  line L30 (-95.9317, 23.5057) -> (-106.2762, 11.1776)
  line L31 (-64.8417, 0.519) -> (-68.8417, 0.519)
  line L32 (-64.8417, -2.0584) -> (-64.8417, 0.519)
  line L33 (-131.7813, -2.0584) -> (-64.8417, -2.0584)
  line L34 (-135.9799, -2.0408) -> (-131.7813, -2.0584)
  line L35 (-135.981, 0.3416) -> (-135.9799, -2.0408)
  line L36 (-131.9809, 0.3416) -> (-135.981, 0.3416)
  line L37 (-131.9809, 7.7) -> (-131.9809, 0.3416)
  line L38 (-117.9809, 7.7) -> (-131.9809, 7.7)
  line L39 (-117.9809, 13.327) -> (-117.9809, 7.7)
  line L40 (-110.2064, 13.3789) -> (-117.9809, 13.327)
  line L41 (-110.1903, 10.979) -> (-110.2064, 13.3789)
  line L42 (-115.5809, 10.9429) -> (-110.1903, 10.979)
  line L43 (-115.5809, 5.3) -> (-115.5809, 10.9429)
  line L44 (-129.5809, 5.3) -> (-115.5809, 5.3)
  line L45 (-129.5809, 0.3416) -> (-129.5809, 5.3)
  line L46 (-71.2417, 0.3416) -> (-129.5809, 0.3416)
  line L47 (-71.2417, 9.8002) -> (-71.2417, 0.3416)
  line L48 (-89.1319, 9.8214) -> (-71.2417, 9.8002)
  line L49 (-89.1317, 10.0006) -> (-89.1319, 9.8214)
  line L50 (-68.8417, 12.1974) -> (-89.1291, 12.2214)
  line L51 (-68.8417, 0.519) -> (-68.8417, 12.1974)
  line L52 (-100.6425, 11.0422) -> (-100.6425, 9.9351)
  line L53 (-106.4895, 11.079) -> (-100.6425, 11.0422)
  line L54 (-95.8944, 23.7057) -> (-106.4895, 11.079)
  line L55 (-88.7317, 23.7057) -> (-95.8944, 23.7057)
  line L56 (-100.6425, 9.9351) -> (-88.7317, 9.8994)
  line L57 (-88.7317, 12.0209) -> (-88.7317, 23.7057)
  line L58 (-88.7317, 9.8994) -> (-88.7317, 10.0209)
  circle C1 centre (-94.4863, 14.2587) radius 1
  point P61 (-89.1317, 10.0006)
  point P62 (-88.7317, 12.0209)
  point P63 (-88.7317, 10.0209)
  horizontal L1
  perpendicular L1 L2
  perpendicular L2 L3
  coincident L27 P61
  coincident L21 P62
  coincident L19 P63
  collinear L57 L58
place_component sketch "Sketch2"
extrude "Extrude1" new body sketch "Sketch2" profile of L1 L2 L3 L4 L5 L6 L7 L8 L9 L10 L12 L13 L14 L15 L16 L17 L18 L19 L22 L23 L24 L25 L26 L27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 along normal blind 4
sketch "Sketch2" plane through (22.9964, 0, 0) normal (-1, 0, 0) x axis (0, -1, 0)
  line L1 (94.7371, 10.0174) -> (99.0604, 10.0174)
  line L2 (99.0604, 10.0304) -> (94.7371, 10.0174)
  line L3 (99.0604, 10.0174) -> (99.0604, 10.0304)
  line L4 (99.0604, 12.0068) -> (99.0604, 11.9976)
  line L5 (105.5881, 11.9976) -> (99.0604, 12.0068)
  line L6 (99.0604, 11.9976) -> (105.5881, 11.9976)
  line L7 (117.7809, 13.1283) -> (117.7809, 7.5)
  line L8 (110.4051, 13.1283) -> (117.7809, 13.1283)
  line L9 (110.4051, 11.1776) -> (110.4051, 13.1283)
  line L10 (110.3917, 11.1776) -> (110.4051, 11.1776)
  line L11 (110.3917, 13.1283) -> (110.3917, 11.1776)
  line L12 (104.6394, 13.1283) -> (110.3917, 13.1283)
  line L13 (95.9317, 23.5057) -> (104.6394, 13.1283)
  line L14 (88.9317, 23.5057) -> (95.9317, 23.5057)
  line L15 (88.9317, 12.0211) -> (88.9317, 23.5057)
  line L16 (88.9374, 12.0211) -> (88.9317, 12.0211)
  line L17 (88.9374, 11.9976) -> (88.9374, 12.0211)
  line L18 (69.0417, 11.9976) -> (88.9374, 11.9976)
  line L19 (69.0417, 0.319) -> (69.0417, 11.9976)
  line L20 (65.0417, 0.319) -> (69.0417, 0.319)
  line L21 (65.0417, -1.8584) -> (65.0417, 0.319)
  line L22 (131.7809, -1.8584) -> (65.0417, -1.8584)
  line L23 (135.78, -1.8416) -> (131.7809, -1.8584)
  line L24 (135.7809, 0.1416) -> (135.78, -1.8416)
  line L25 (131.7809, 0.1416) -> (135.7809, 0.1416)
  line L26 (131.7809, 7.5) -> (131.7809, 0.1416)
  line L27 (117.7809, 7.5) -> (131.7809, 7.5)
  line L28 (85.7317, 15.1976) -> (85.7317, 26.7057)
  line L29 (65.8417, 15.1976) -> (85.7317, 15.1976)
  line L30 (65.8417, 3.519) -> (65.8417, 15.1976)
  line L31 (61.8417, 3.519) -> (65.8417, 3.519)
  line L32 (61.8417, -5.0584) -> (61.8417, 3.519)
  line L33 (131.7876, -5.0584) -> (61.8417, -5.0584)
  line L34 (138.9786, -5.0282) -> (131.7876, -5.0584)
  line L35 (138.9824, 3.3416) -> (138.9786, -5.0282)
  line L36 (134.9809, 3.3416) -> (138.9824, 3.3416)
  line L37 (134.9809, 10.7) -> (134.9809, 3.3416)
  line L38 (120.9809, 10.7) -> (134.9809, 10.7)
  line L39 (120.9809, 16.3283) -> (120.9809, 10.7)
  line L40 (113.5917, 16.3283) -> (120.9809, 16.3283)
  line L41 (107.2051, 16.3283) -> (113.5917, 16.3283)
  line L42 (106.1316, 16.3283) -> (107.2051, 16.3283)
  line L43 (97.4239, 26.7057) -> (106.1316, 16.3283)
  line L44 (85.7317, 26.7057) -> (97.4239, 26.7057)
  dimension "d202" = 3.2
extrude "Extrude1" new body sketch "Sketch2" profile of L1 L2 L3 L4 L5 L6 L7 L8 L9 L10 L11 L12 L13 L14 L15 L16 L17 L18 L19 L20 L21 L22 L23 L24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 along normal blind 3
shell "Shell1" innerThickness 2
sketch "Sketch3" plane through (0, -101.0604, 0) normal (0, -1, 0) x axis (1, 0, 0)
  line L1 (19.9964, 9.9976) -> (20.9964, 9.9976)
  line L2 (19.9964, 8.0174) -> (19.9964, 9.9976)
  line L3 (20.9964, 8.0174) -> (19.9964, 8.0174)
  line L4 (20.9964, 9.9976) -> (20.9964, 8.0174)
extrude "Extrude2" cut of existing geometry to an object
extrude "Extrude3" cut of existing geometry to an object
extrude "Extrude4" cut of existing geometry to an object
sketch "Sketch4" plane through (20.9964, 0, 0) normal (-1, 0, 0) x axis (0, -1, 0)
  line L1 (118.9809, 14.3283) -> (118.9809, 8.7)
  line L2 (105.199, 14.3283) -> (118.9809, 14.3283)
  line L3 (96.4913, 24.7057) -> (105.199, 14.3283)
  line L4 (87.7317, 24.7057) -> (96.4913, 24.7057)
  line L5 (87.7317, 13.1976) -> (87.7317, 24.7057)
  line L6 (67.8417, 13.1976) -> (87.7317, 13.1976)
  line L7 (67.8417, 1.519) -> (67.8417, 13.1976)
  line L8 (63.8417, 1.519) -> (67.8417, 1.519)
  line L9 (63.8417, -3.0584) -> (63.8417, 1.519)
  line L10 (131.7834, -3.0584) -> (63.8417, -3.0584)
  line L11 (136.9795, -3.0366) -> (131.7834, -3.0584)
  line L12 (136.9815, 1.3416) -> (136.9795, -3.0366)
  line L13 (132.9809, 1.3416) -> (136.9815, 1.3416)
  line L14 (132.9809, 8.7) -> (132.9809, 1.3416)
  line L15 (118.9809, 8.7) -> (132.9809, 8.7)
  line L16 (94.7371, 10.0174) -> (99.0604, 10.0174)
  line L17 (99.0604, 10.0304) -> (94.7371, 10.0174)
  line L18 (99.0604, 10.0174) -> (99.0604, 10.0304)
  line L19 (99.0604, 12.0068) -> (99.0604, 11.9976)
  line L20 (105.5881, 11.9976) -> (99.0604, 12.0068)
  line L21 (99.0604, 11.9976) -> (105.5881, 11.9976)
extrude "Extrude5" cut sketch "Sketch1" profile of C1 to an object
extrude "Extrude6" add of existing geometry blind -6
extrude "Extrude7" cut of existing geometry to an object
sketch "Sketch5" plane through (22.9964, 0, 0) normal (1, 0, 0) x axis (0, 1, 0)
  line L1 (-132.9809, 8.7) -> (-118.9809, 8.7)
  line L2 (-132.9809, 1.3416) -> (-132.9809, 8.7)
  line L3 (-136.9815, 1.3416) -> (-132.9809, 1.3416)
  line L4 (-136.9795, -3.0366) -> (-136.9815, 1.3416)
  line L5 (-131.7834, -3.0584) -> (-136.9795, -3.0366)
  line L6 (-63.8417, -3.0584) -> (-131.7834, -3.0584)
  line L7 (-63.8417, 1.519) -> (-63.8417, -3.0584)
  line L8 (-67.8417, 1.519) -> (-63.8417, 1.519)
  line L9 (-67.8417, 13.1976) -> (-67.8417, 1.519)
  line L10 (-87.7317, 13.1976) -> (-67.8417, 13.1976)
  line L11 (-87.7317, 24.7057) -> (-87.7317, 13.1976)
  line L12 (-96.4913, 24.7057) -> (-87.7317, 24.7057)
  line L13 (-105.199, 14.3283) -> (-96.4913, 24.7057)
  line L14 (-118.9809, 14.3283) -> (-105.199, 14.3283)
  line L15 (-118.9809, 8.7) -> (-118.9809, 14.3283)
  line L16 (-94.7371, 10.0174) -> (-99.0604, 10.0304)
  line L17 (-99.0604, 10.0174) -> (-94.7371, 10.0174)
  line L18 (-99.0604, 10.0304) -> (-99.0604, 10.0174)
  line L19 (-99.0604, 12.0068) -> (-105.5881, 11.9976)
  line L20 (-99.0604, 11.9976) -> (-99.0604, 12.0068)
  line L21 (-105.5881, 11.9976) -> (-99.0604, 11.9976)
  circle C1 centre (-94.4863, 14.2587) radius 1
sketch "Sketch6" plane through (20.9964, 0, 0) normal (-1, 0, 0) x axis (0, -1, 0)
  line L1 (85.7317, 15.1976) -> (85.7317, 26.7057)
  line L2 (65.8417, 15.1976) -> (85.7317, 15.1976)
  line L3 (65.8417, 3.519) -> (65.8417, 15.1976)
  line L4 (61.8417, 3.519) -> (65.8417, 3.519)
  line L5 (61.8417, -5.0584) -> (61.8417, 3.519)
  line L6 (131.7876, -5.0584) -> (61.8417, -5.0584)
  line L7 (138.9786, -5.0282) -> (131.7876, -5.0584)
  line L8 (138.9824, 3.3416) -> (138.9786, -5.0282)
  line L9 (134.9809, 3.3416) -> (138.9824, 3.3416)
  line L10 (134.9809, 10.7) -> (134.9809, 3.3416)
  line L11 (120.9809, 10.7) -> (134.9809, 10.7)
  line L12 (120.9809, 16.3283) -> (120.9809, 10.7)
  line L13 (106.1316, 16.3283) -> (120.9809, 16.3283)
  line L14 (97.4239, 26.7057) -> (106.1316, 16.3283)
  line L15 (85.7317, 26.7057) -> (97.4239, 26.7057)
  line L16 (94.7371, 10.0174) -> (99.0604, 10.0174)
  line L17 (99.0604, 10.0304) -> (94.7371, 10.0174)
  line L18 (99.0604, 10.0174) -> (99.0604, 10.0304)
  line L19 (99.0604, 12.0068) -> (99.0604, 11.9976)
  line L20 (105.5881, 11.9976) -> (99.0604, 12.0068)
  line L21 (99.0604, 11.9976) -> (105.5881, 11.9976)
  line L22 (137.9819, 2.3416) -> (137.979, -4.0324)
  line L23 (133.9809, 2.3416) -> (137.9819, 2.3416)
  line L24 (133.9809, 9.7) -> (133.9809, 2.3416)
  line L25 (119.9809, 9.7) -> (133.9809, 9.7)
  line L26 (119.9809, 15.3283) -> (119.9809, 9.7)
  line L27 (105.6653, 15.3283) -> (119.9809, 15.3283)
  line L28 (96.9576, 25.7057) -> (105.6653, 15.3283)
  line L29 (86.7317, 25.7057) -> (96.9576, 25.7057)
  line L30 (86.7317, 14.1976) -> (86.7317, 25.7057)
  line L31 (66.8417, 14.1976) -> (86.7317, 14.1976)
  line L32 (66.8417, 2.519) -> (66.8417, 14.1976)
  line L33 (62.8417, 2.519) -> (66.8417, 2.519)
  line L34 (62.8417, -4.0584) -> (62.8417, 2.519)
  line L35 (131.7855, -4.0584) -> (62.8417, -4.0584)
  line L36 (137.979, -4.0324) -> (131.7855, -4.0584)
  circle C1 centre (94.4863, 14.2587) radius 1
  dimension "d218" = -1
